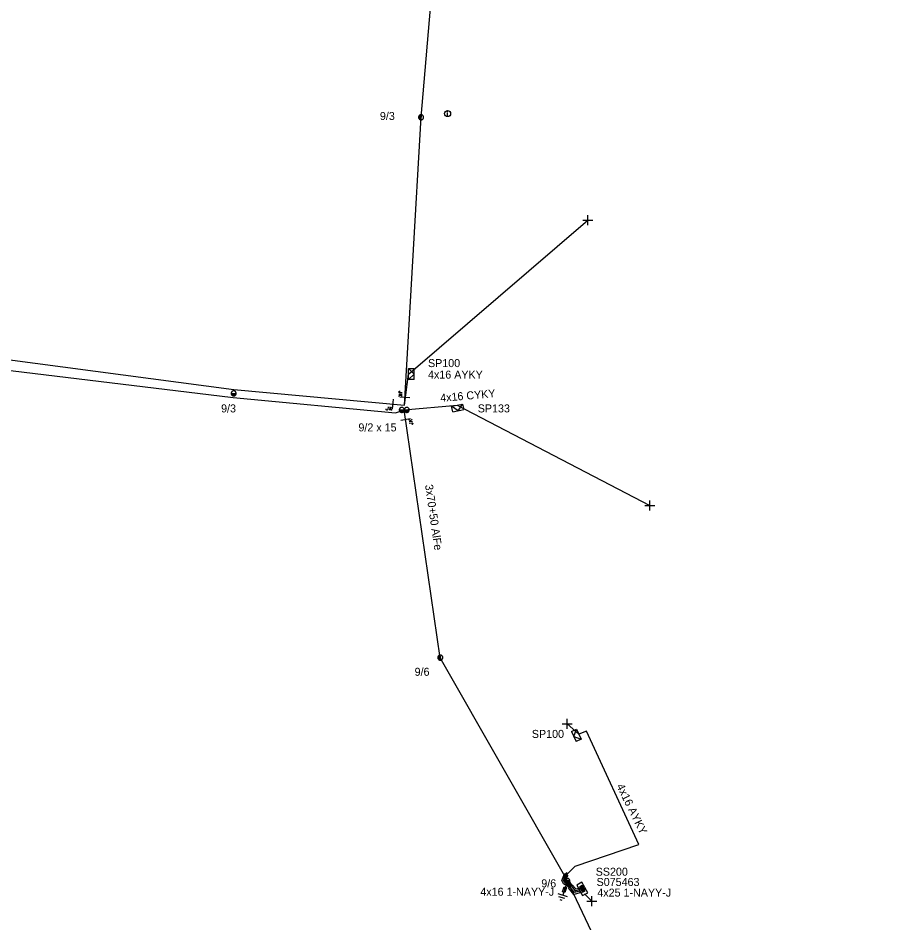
# Model space of a CAD drawing. Extents: x -717562 to -713845, y -1151196 to -1143903.
# Drawn here: x -714167.1 to -714057.9, y -1147096.8 to -1146983.8 of the extents above; entities that cross this region are included whole.
import ezdxf

# ---------------------------------------------------------------- set-up
doc = ezdxf.new("R2010")
doc.units = 0
for name, color, linetype in [('Vrstva 1', 7, 'Continuous'), ('Vrstva 10', 7, 'Continuous'), ('Vrstva 12', 7, 'Continuous'), ('Vrstva 13', 7, 'Continuous'), ('Vrstva 14', 7, 'Continuous'), ('Vrstva 15', 7, 'Continuous'), ('Vrstva 16', 7, 'Continuous'), ('Vrstva 18', 7, 'Continuous'), ('Vrstva 19', 7, 'Continuous'), ('Vrstva 2', 7, 'Continuous'), ('Vrstva 20', 7, 'Continuous'), ('Vrstva 28', 7, 'Continuous'), ('Vrstva 29', 7, 'Continuous'), ('Vrstva 30', 7, 'Continuous'), ('Vrstva 31', 7, 'Continuous'), ('Vrstva 33', 7, 'Continuous'), ('Vrstva 34', 7, 'Continuous'), ('Vrstva 36', 7, 'Continuous'), ('Vrstva 4', 7, 'Continuous'), ('Vrstva 5', 7, 'Continuous'), ('Vrstva 50', 7, 'Continuous'), ('Vrstva 52', 7, 'Continuous'), ('Vrstva 54', 7, 'Continuous'), ('Vrstva 59', 7, 'Continuous'), ('Vrstva 6', 7, 'Continuous'), ('Vrstva 8', 7, 'Continuous'), ('Vrstva 9', 7, 'Continuous')]:
    doc.layers.add(name, color=color, linetype=linetype)

# ---------------------------------------------------------------- blocks, each defined once
blk = doc.blocks.new('NN440')
at = {"layer": 'Vrstva 2'}
for points in [[(0.63, 0), (0.63, 0.06), (0.62, 0.13), (0.6, 0.19), (0.58, 0.25), (0.55, 0.31), (0.51, 0.37), (0.47, 0.42), (0.42, 0.46), (0.37, 0.51), (0.32, 0.54), (0.26, 0.57), (0.2, 0.59), (0.13, 0.61), (0.07, 0.62), (0, 0.63), (-0.06, 0.62), (-0.13, 0.61), (-0.19, 0.59), (-0.26, 0.57), (-0.31, 0.54), (-0.37, 0.51), (-0.42, 0.46), (-0.47, 0.42), (-0.51, 0.37), (-0.54, 0.31), (-0.57, 0.25), (-0.6, 0.19), (-0.62, 0.13), (-0.63, 0.06), (-0.63, 0), (-0.63, -0.07), (-0.62, -0.14), (-0.6, -0.2), (-0.57, -0.26), (-0.54, -0.32), (-0.51, -0.37), (-0.47, -0.43), (-0.42, -0.47), (-0.37, -0.51), (-0.31, -0.55), (-0.26, -0.58), (-0.19, -0.6), (-0.13, -0.62), (-0.06, -0.63), (0, -0.63), (0.07, -0.63), (0.13, -0.62), (0.2, -0.6), (0.26, -0.58), (0.32, -0.55), (0.37, -0.51), (0.42, -0.47), (0.47, -0.43), (0.51, -0.37), (0.55, -0.32), (0.58, -0.26), (0.6, -0.2), (0.62, -0.14), (0.63, -0.07), (0.63, 0)], [(-0.63, 0), (0.63, 0)], [(-0.6, -0.18), (0.57, -0.18)], [(-0.51, -0.32), (0.5, -0.32)], [(-0.37, -0.47), (0.35, -0.47)]]:
    blk.add_lwpolyline(points, dxfattribs=at)
blk = doc.blocks.new('NN450')
at = {"layer": 'Vrstva 2'}
for points in [[(0, 0), (0, 0.07), (-0.01, 0.13), (-0.03, 0.19), (-0.05, 0.25), (-0.08, 0.31), (-0.12, 0.37), (-0.16, 0.42), (-0.21, 0.46), (-0.26, 0.51), (-0.31, 0.54), (-0.37, 0.57), (-0.43, 0.59), (-0.5, 0.61), (-0.56, 0.62), (-0.63, 0.62), (-0.69, 0.62), (-0.75, 0.61), (-0.82, 0.59), (-0.88, 0.57), (-0.94, 0.54), (-0.99, 0.51), (-1.04, 0.46), (-1.09, 0.42), (-1.13, 0.37), (-1.17, 0.31), (-1.2, 0.25), (-1.22, 0.19), (-1.24, 0.13), (-1.25, 0.07), (-1.25, 0), (-1.25, -0.07), (-1.24, -0.13), (-1.22, -0.19), (-1.2, -0.25), (-1.17, -0.31), (-1.13, -0.37), (-1.09, -0.42), (-1.04, -0.46), (-0.99, -0.51), (-0.94, -0.54), (-0.88, -0.57), (-0.82, -0.59), (-0.75, -0.61), (-0.69, -0.62), (-0.62, -0.63), (-0.56, -0.62), (-0.5, -0.61), (-0.43, -0.59), (-0.37, -0.57), (-0.31, -0.54), (-0.26, -0.51), (-0.21, -0.46), (-0.16, -0.42), (-0.12, -0.37), (-0.08, -0.31), (-0.05, -0.25), (-0.03, -0.19), (-0.01, -0.13), (0, -0.07), (0, 0)], [(1.25, 0), (1.25, 0.07), (1.24, 0.13), (1.22, 0.19), (1.2, 0.25), (1.17, 0.31), (1.13, 0.37), (1.09, 0.42), (1.04, 0.46), (0.99, 0.51), (0.94, 0.54), (0.88, 0.57), (0.82, 0.59), (0.75, 0.61), (0.69, 0.62), (0.62, 0.62), (0.56, 0.62), (0.5, 0.61), (0.43, 0.59), (0.37, 0.57), (0.31, 0.54), (0.26, 0.51), (0.21, 0.46), (0.16, 0.42), (0.12, 0.37), (0.08, 0.31), (0.05, 0.25), (0.03, 0.19), (0.01, 0.13), (0, 0.07), (0, 0), (0, -0.07), (0.01, -0.13), (0.03, -0.19), (0.05, -0.25), (0.08, -0.31), (0.12, -0.37), (0.16, -0.42), (0.21, -0.46), (0.26, -0.51), (0.31, -0.54), (0.37, -0.57), (0.43, -0.59), (0.5, -0.61), (0.56, -0.62), (0.63, -0.63), (0.69, -0.62), (0.75, -0.61), (0.82, -0.59), (0.88, -0.57), (0.94, -0.54), (0.99, -0.51), (1.04, -0.46), (1.09, -0.42), (1.13, -0.37), (1.17, -0.31), (1.2, -0.25), (1.22, -0.19), (1.24, -0.13), (1.25, -0.07), (1.25, 0)], [(-1.25, 0), (1.25, 0)], [(-1.23, -0.16), (-0.02, -0.16)], [(-1.16, -0.32), (-0.09, -0.32)], [(-1.03, -0.47), (-0.22, -0.47)], [(0.02, -0.16), (1.23, -0.16)], [(0.09, -0.32), (1.16, -0.32)], [(0.22, -0.47), (1.03, -0.47)]]:
    blk.add_lwpolyline(points, dxfattribs=at)
blk = doc.blocks.new('NN840')
at = {"layer": 'Vrstva 15'}
for points in [[(0, 0.62), (0, -0.63)], [(-0.75, -0.71), (-0.75, -0.66)], [(-0.73, -0.76), (-0.75, -0.71)], [(-0.66, -0.8), (-0.73, -0.76)], [(-0.63, -0.8), (-0.66, -0.8)], [(-0.56, -0.76), (-0.63, -0.8)], [(-0.54, -0.71), (-0.56, -0.76)], [(-0.54, -0.38), (-0.54, -0.71)], [(-0.33, -0.38), (-0.33, -0.8)], [(-0.33, -0.64), (-0.13, -0.38)], [(-0.26, -0.56), (-0.09, -0.8)]]:
    blk.add_lwpolyline(points, dxfattribs=at)
blk = doc.blocks.new('NN770')
at = {"layer": 'Vrstva 10'}
for p, q in [((0, 0.19), (0, 0.26)), ((0, -0.28), (0, 0.11))]:
    blk.add_line(p, q, dxfattribs=at)
blk.add_circle((0, -0.01), 0.375, dxfattribs=at)
blk = doc.blocks.new('NN870')
at = {"layer": 'Vrstva 4'}
for points in [[(0, -0.25), (0.5, 0), (0, 0.25), (-0.5, 0), (0, -0.25)], [(0.37, 0), (0, 0.19), (-0.36, 0), (0, -0.19), (0.37, 0)], [(0.24, 0), (0, 0.12), (-0.25, 0), (0, -0.12), (0.24, 0)], [(0.12, 0), (0, 0.06), (-0.13, 0), (0, -0.06), (0.12, 0)]]:
    blk.add_lwpolyline(points, dxfattribs=at)
blk = doc.blocks.new('NN800')
at = {"layer": 'Vrstva 1'}
for points in [[(-0.44, 0.44), (0.44, -0.44)], [(-0.44, -0.44), (0.44, 0.44)]]:
    blk.add_lwpolyline(points, dxfattribs=at)
blk = doc.blocks.new('NN820')
at = {"layer": 'Vrstva 13'}
for points in [[(0, 0), (0, -1.05)], [(-0.16, -0.81), (0.16, -0.81)], [(-0.16, -1.47), (-0.16, -0.81)], [(0, -1.05), (-0.06, -0.93)], [(0, -1.05), (0.06, -0.93)], [(0.16, -0.81), (0.16, -1.47)], [(0.16, -1.47), (-0.16, -1.47)], [(0, -1.47), (0, -1.87)]]:
    blk.add_lwpolyline(points, dxfattribs=at)
blk = doc.blocks.new('NN620')
at = {"layer": 'Vrstva 8'}
for points in [[(0.75, 0), (-0.75, 0)], [(-0.75, 0), (-0.75, -0.75)], [(0.75, -0.75), (0.75, 0)], [(-0.75, -0.75), (0.75, -0.75)], [(0.37, -0.18), (-0.38, -0.18)], [(-0.38, -0.18), (-0.38, -0.56)], [(-0.38, -0.56), (0.37, -0.56)], [(0.32, -0.23), (-0.33, -0.23)], [(-0.33, -0.23), (-0.33, -0.51)], [(-0.33, -0.51), (0.32, -0.51)], [(0.27, -0.27), (-0.28, -0.27)], [(-0.28, -0.27), (-0.28, -0.46)], [(-0.28, -0.46), (0.27, -0.46)], [(0.23, -0.32), (-0.23, -0.32)], [(-0.23, -0.32), (-0.23, -0.42)], [(-0.23, -0.42), (0.23, -0.42)], [(-0.19, -0.37), (0.19, -0.37)], [(0.23, -0.42), (0.23, -0.32)], [(0.27, -0.46), (0.27, -0.27)], [(0.32, -0.51), (0.32, -0.23)], [(0.37, -0.56), (0.37, -0.18)]]:
    blk.add_lwpolyline(points, dxfattribs=at)
blk = doc.blocks.new('NN630')
at = {"layer": 'Vrstva 9'}
for points in [[(0, -0.7), (-0.7, 0)], [(-0.7, -0.7), (-0.7, 0), (0.7, 0), (0.7, -0.7)], [(-0.7, -0.7), (0.7, -0.7)], [(0, -0.7), (0.7, 0)]]:
    blk.add_lwpolyline(points, dxfattribs=at)
blk = doc.blocks.new('NN810')
at = {"layer": 'Vrstva 14'}
for points in [[(0, -0.64), (0, -1.89)], [(0.63, -1.89), (-0.62, -1.89)], [(0.39, -2.2), (-0.4, -2.2)], [(0, -2.52), (-0.12, -2.52)], [(0.14, -2.52), (0, -2.52)]]:
    blk.add_lwpolyline(points, dxfattribs=at)

msp = doc.modelspace()

# ---------------------------------------------------------------- linework, layer by layer
at = {"layer": 'Vrstva 1'}
for points in [[(-714118.86, -1147032.12), (-714116.8, -1146996.15), (-714114.09, -1146964.48), (-714111.65, -1146933.33), (-714114.99, -1146895.94)], [(-714265.43, -1147021.34), (-714222.41, -1147023.52), (-714178.81, -1147025.04), (-714140.15, -1147030.14), (-714118.86, -1147032.12)], [(-714098.54, -1147091.52), (-714114.4, -1147063.64), (-714118.9, -1147032.69)], [(-713984.48, -1147194.64), (-714024.75, -1147174.82), (-714056.47, -1147154.69), (-714081.76, -1147126.93), (-714098.54, -1147091.52)]]:
    msp.add_lwpolyline(points, dxfattribs=at)
at = {"layer": 'Vrstva 20'}
for points in [[(-714098.27, -1147092.35), (-714099.04, -1147091.9), (-714099.24, -1147091.45), (-714098.98, -1147090.85), (-714098.62, -1147091.01), (-714098.8, -1147091.45), (-714098.72, -1147091.62), (-714098.07, -1147092.01)], [(-714098.95, -1147090.8), (-714098.77, -1147090.59), (-714098.47, -1147090.85), (-714098.65, -1147091.06)], [(-714098.37, -1147091.42), (-714098, -1147092.08), (-714098.34, -1147092.28), (-714098.71, -1147091.62)], [(-714096.94, -1147092.99), (-714097.73, -1147093.2), (-714098.4, -1147092.37), (-714097.94, -1147091.99), (-714097.51, -1147092.52), (-714097.1, -1147092.41)]]:
    msp.add_lwpolyline(points, close=True, dxfattribs=at)
at = {"layer": 'Vrstva 5'}
msp.add_lwpolyline([(-714098.54, -1147091.52), (-714098.09, -1147092.12), (-714097.58, -1147092.75), (-714097.07, -1147092.61)], dxfattribs=at)
at = {"layer": 'Vrstva 50'}
msp.add_lwpolyline([(-714265.35, -1147022.3), (-714222.47, -1147024.52), (-714179.05, -1147026.46), (-714140.24, -1147031.13), (-714120, -1147033.08), (-714118.9, -1147032.69)], dxfattribs=at)
at = {"layer": 'Vrstva 52'}
for points in [[(-714118.86, -1147032.12), (-714118.38, -1147028.22)], [(-714118.9, -1147032.69), (-714112.3, -1147032.11)], [(-714098.8, -1147090.93), (-714098.62, -1147090.72), (-714097.57, -1147089.69), (-714089.61, -1147086.98), (-714096.17, -1147072.83), (-714097.1, -1147073.19)], [(-714096.99, -1147092.8), (-714097.66, -1147092.97), (-714098.42, -1147092.03), (-714098.88, -1147091.76), (-714099.02, -1147091.45), (-714098.8, -1147090.93)]]:
    msp.add_lwpolyline(points, dxfattribs=at)
at = {"layer": 'Vrstva 59'}
for points in [[(-714118.38, -1147028.22), (-714096, -1147009)], [(-714112.3, -1147032.11), (-714088.25, -1147044.63)], [(-714097.1, -1147073.19), (-714098.59, -1147071.91)], [(-714096.4, -1147093.13), (-714095.51, -1147094.03)]]:
    msp.add_lwpolyline(points, dxfattribs=at)

# ---------------------------------------------------------------- block references
at = {"layer": 'Vrstva 13'}
for p, xscale, yscale, rotation in [((-714116.8, -1146996.15), 0.49999999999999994, 0.5000000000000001, -93.29142508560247), ((-714140.19, -1147030.63), 0.5000000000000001, 0.5, -5.520708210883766), ((-714114.4, -1147063.63), 0.5, 0.49999999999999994, -81.72892223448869), ((-714098.54, -1147091.52), 0.5, 0.5, -61.196650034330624)]:
    msp.add_blockref('NN440', p, dxfattribs=dict(at, xscale=xscale, yscale=yscale, rotation=rotation))
at = {"layer": 'Vrstva 13', "xscale": 0.5, "yscale": 0.5}
msp.add_blockref('NN450', (-714118.9, -1147032.69), dxfattribs=at)
at = {"layer": 'Vrstva 15', "rotation": -18.041533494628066}
msp.add_blockref('NN810', (-714098.54, -1147091.52), dxfattribs=at)
at = {"layer": 'Vrstva 16', "rotation": -18.041533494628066}
msp.add_blockref('NN820', (-714098.54, -1147091.52), dxfattribs=at)
at = {"layer": 'Vrstva 18'}
for p, rotation in [((-714118.81, -1147031.14), -93.29053890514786), ((-714120.35, -1147031.98), -5.326216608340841), ((-714118.73, -1147033.88), 98.27107776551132)]:
    msp.add_blockref('NN840', p, dxfattribs=dict(at, rotation=rotation))
at = {"layer": 'Vrstva 19', "rotation": 67.06789956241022}
msp.add_blockref('NN870', (-714098.8, -1147090.93), dxfattribs=at)
at = {"layer": 'Vrstva 28', "rotation": 119.16902054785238}
msp.add_blockref('NN620', (-714097.02, -1147092.7), dxfattribs=at)
at = {"layer": 'Vrstva 31'}
for p, rotation in [((-714118.38, -1147028.22), 90), ((-714112.3, -1147032.11), 11.153519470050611), ((-714097.1, -1147073.19), -65.71417475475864)]:
    msp.add_blockref('NN630', p, dxfattribs=dict(at, rotation=rotation))
at = {"layer": 'Vrstva 34'}
for p, rotation in [((-714096, -1147009), 45), ((-714088.25, -1147044.63), 45), ((-714098.59, -1147071.91), 45), ((-714095.51, -1147094.03), 44.99999995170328)]:
    msp.add_blockref('NN800', p, dxfattribs=dict(at, rotation=rotation))
at = {"layer": 'Vrstva 36'}
msp.add_blockref('NN770', (-714113.49, -1146995.68), dxfattribs=at)

# ---------------------------------------------------------------- texts
at = {"layer": 'Vrstva 12'}
for s, p in [('9/3', (-714121.94, -1146996.49)), ('9/3', (-714141.76, -1147033.01)), ('9/2 x 15', (-714124.62, -1147035.38)), ('9/6', (-714117.61, -1147065.9)), ('9/6', (-714101.8, -1147092.32))]:
    msp.add_text(s, height=1, dxfattribs=at).set_placement(p)
at = {"layer": 'Vrstva 2'}
msp.add_text('3x70+50 AlFe', height=1, rotation=278.271, dxfattribs=at).set_placement((-714116.32, -1147042.08))
at = {"layer": 'Vrstva 29'}
msp.add_text('S075463', height=1, dxfattribs=at).set_placement((-714094.9, -1147092.15))
at = {"layer": 'Vrstva 30'}
msp.add_text('SS200', height=1, dxfattribs=at).set_placement((-714095.01, -1147090.87))
at = {"layer": 'Vrstva 33'}
for s, p in [('SP100', (-714115.94, -1147027.35)), ('SP133', (-714109.73, -1147033.01)), ('SP100', (-714102.98, -1147073.66))]:
    msp.add_text(s, height=1, dxfattribs=at).set_placement(p)
at = {"layer": 'Vrstva 54'}
for s, p in [('4x16 AYKY', (-714115.94, -1147028.79)), ('4x16 1-NAYY-J', (-714109.41, -1147093.37))]:
    msp.add_text(s, height=1, dxfattribs=at).set_placement(p)
for s, rotation, p in [('4x16 CYKY', 5.082, (-714114.37, -1147031.71)), ('4x16 AYKY', 296.243, (-714092.45, -1147079.68))]:
    msp.add_text(s, height=1, rotation=rotation, dxfattribs=at).set_placement(p)
at = {"layer": 'Vrstva 6'}
msp.add_text('4x25 1-NAYY-J', height=1, dxfattribs=at).set_placement((-714094.81, -1147093.48))

doc.saveas('drawing.dxf')
